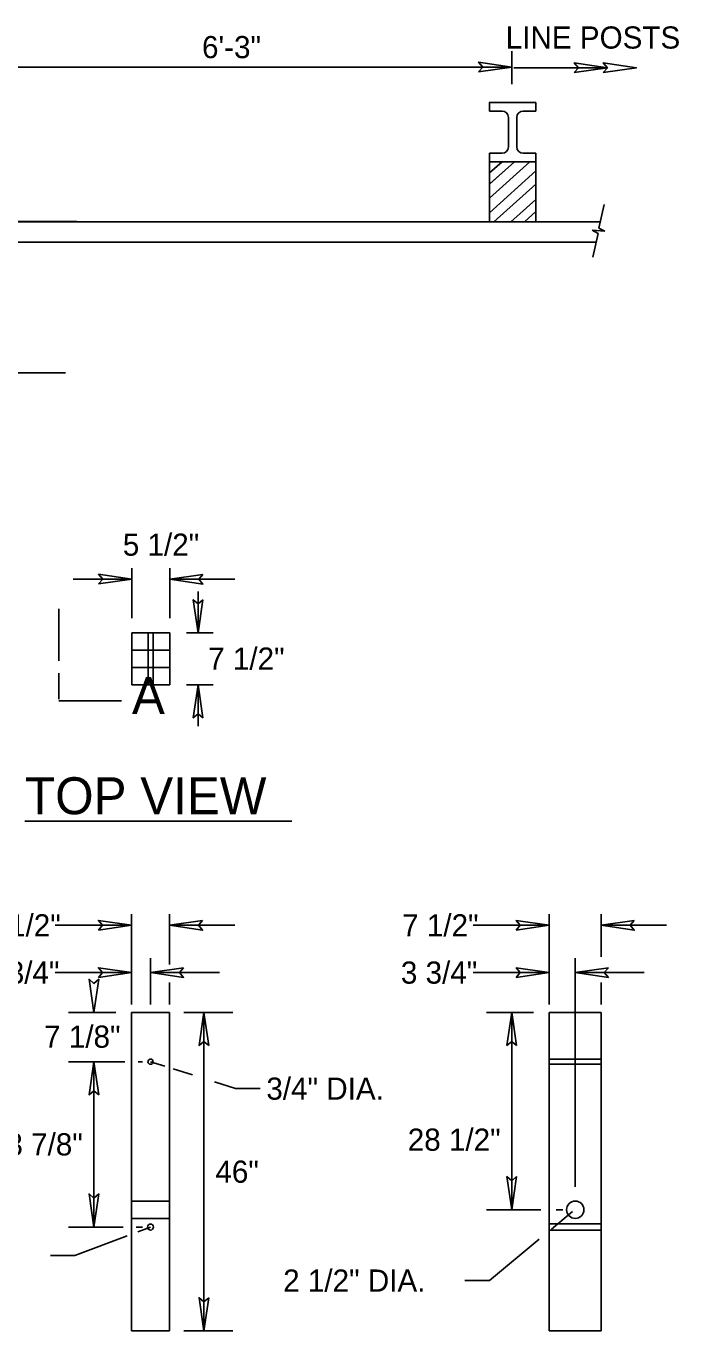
# Model space of a CAD drawing. Extents: x 12.2 to 54.5, y -7.8 to 16.1.
# Drawn here: x 15.188 to 16.956, y 9.039 to 12.571 of the extents above; entities that cross this region are included whole.
import ezdxf

# ---------------------------------------------------------------- set-up
doc = ezdxf.new("R2010")
doc.units = 0
for name, color, linetype in [('BORD-LINE', 7, 'Continuous'), ('DETAIL DIM', 7, 'Continuous'), ('DETL-DIMS', 7, 'Continuous'), ('DETL-LINE', 7, 'Continuous'), ('DETL-NOTE', 7, 'Continuous'), ('DETL-TITL', 7, 'Continuous')]:
    doc.layers.add(name, color=color, linetype=linetype)

msp = doc.modelspace()

# ---------------------------------------------------------------- linework, layer by layer
at = {"layer": 'BORD-LINE'}
for p, q in [((16.7391, 12.0246), (16.7531, 12.0888)), ((16.7435, 12.0412), (12.8535, 12.0414)), ((15.3256, 12.0419), (15.1457, 12.0419)), ((15.3257, 12.0417), (15.1457, 12.0417)), ((16.7205, 12.0189), (16.7555, 12.016)), ((16.7369, 12.0103), (16.7205, 12.0189)), ((16.7555, 12.016), (16.7391, 12.0246)), ((16.7308, 11.9868), (12.7636, 11.9868)), ((16.7229, 11.9461), (16.7369, 12.0103)), ((15.5768, 10.9288), (15.4737, 10.9288)), ((15.4737, 10.9288), (15.4737, 10.7882)), ((15.5768, 10.7882), (15.5768, 10.9288)), ((15.4737, 10.7882), (15.5768, 10.7882)), ((15.4732, 9.9011), (15.4732, 9.0386)), ((15.4732, 9.9011), (15.5763, 9.9011)), ((15.5763, 9.9011), (15.5763, 9.0386)), ((16.6047, 9.9011), (16.6047, 9.0386)), ((16.6047, 9.9011), (16.7453, 9.9011)), ((16.7453, 9.9011), (16.7453, 9.0386)), ((15.4732, 9.0386), (15.5763, 9.0386)), ((16.6047, 9.0386), (16.7453, 9.0386))]:
    msp.add_line(p, q, dxfattribs=at)
for centre, radius in [((15.5247, 9.7675), 0.00703), ((16.675, 9.3667), 0.0234), ((15.5247, 9.3198), 0.0082)]:
    msp.add_circle(centre, radius, dxfattribs=at)
for points in [[(15.5182, 10.9288), (15.5182, 10.7882)], [(15.5323, 10.7882), (15.5323, 10.9288)], [(15.5768, 10.8819), (15.4737, 10.8819)], [(15.4737, 10.8351), (15.5768, 10.8351)], [(16.7453, 9.7745), (16.6047, 9.7745)], [(16.6047, 9.7605), (16.7453, 9.7605)], [(15.5763, 9.3902), (15.4732, 9.3902)], [(15.4732, 9.3433), (15.5763, 9.3433)], [(16.7453, 9.3281), (16.6047, 9.3281)], [(16.6047, 9.3116), (16.7453, 9.3116)]]:
    msp.add_open_spline(points, degree=1, dxfattribs=at)
at = {"layer": 'DETAIL DIM'}
for p, q in [((15.4737, 10.9683), (15.4737, 11.1038)), ((15.5768, 10.9683), (15.5768, 11.1038)), ((15.3151, 11.074), (15.4737, 11.074)), ((15.7534, 11.074), (15.5768, 11.074)), ((15.6537, 10.9288), (15.6537, 11.041)), ((15.6221, 10.9288), (15.6942, 10.9288)), ((15.6221, 10.7882), (15.6942, 10.7882)), ((15.6537, 10.7882), (15.6537, 10.676)), ((15.4732, 9.9219), (15.4732, 10.1665)), ((15.5763, 10.031), (15.5763, 10.1665)), ((15.2668, 10.1367), (15.4732, 10.1367)), ((15.7529, 10.1367), (15.5763, 10.1367)), ((16.3983, 10.1367), (16.6047, 10.1367)), ((16.9219, 10.1367), (16.7453, 10.1367)), ((15.5247, 9.9219), (15.5247, 10.0482)), ((15.2668, 10.0088), (15.4732, 10.0088)), ((15.7116, 10.0088), (15.5247, 10.0088)), ((16.3983, 10.0088), (16.6047, 10.0088)), ((16.8619, 10.0088), (16.675, 10.0088)), ((15.5763, 9.9219), (15.5763, 9.9816)), ((15.3029, 9.9011), (15.4306, 9.9011)), ((15.6146, 9.9011), (15.7476, 9.9011)), ((15.6693, 9.0386), (15.6693, 9.9011)), ((16.5029, 9.3667), (16.5029, 9.9011)), ((15.3029, 9.7675), (15.4553, 9.7675)), ((15.3714, 9.7675), (15.3714, 9.3198)), ((15.4913, 9.7675), (15.5031, 9.7675)), ((15.5633, 9.7553), (15.5247, 9.7675)), ((15.6387, 9.7315), (15.5865, 9.748)), ((15.7553, 9.6946), (15.6984, 9.7126)), ((15.7553, 9.6946), (15.8218, 9.6946)), ((16.4344, 9.3667), (16.5817, 9.3667)), ((16.6229, 9.3667), (16.641, 9.3667)), ((15.3029, 9.3198), (15.4504, 9.3198)), ((15.32, 9.2431), (15.4616, 9.2962)), ((15.4855, 9.3198), (15.5031, 9.3198)), ((15.4907, 9.3071), (15.5245, 9.3198)), ((15.32, 9.2431), (15.2536, 9.2431))]:
    msp.add_line(p, q, dxfattribs=at)
at = {"layer": 'DETL-DIMS'}
for p, q in [((16.4132, 12.4738), (16.5028, 12.4606)), ((16.4132, 12.4738), (16.4243, 12.4606)), ((16.5028, 12.5036), (16.5028, 12.4143)), ((16.6724, 12.472), (16.762, 12.4588)), ((16.6724, 12.472), (16.6835, 12.4588)), ((16.7509, 12.472), (16.8405, 12.4588)), ((16.7509, 12.472), (16.762, 12.4588)), ((16.5028, 12.4606), (15.098, 12.4606)), ((16.4132, 12.4477), (16.5028, 12.4606)), ((16.4132, 12.4477), (16.4243, 12.4606)), ((16.762, 12.4588), (16.5084, 12.4588)), ((16.6724, 12.4459), (16.762, 12.4588)), ((16.6724, 12.4459), (16.6835, 12.4588)), ((16.7509, 12.4459), (16.8405, 12.4588)), ((16.7509, 12.4459), (16.762, 12.4588)), ((15.3841, 11.0872), (15.4737, 11.074)), ((15.3841, 11.0872), (15.3952, 11.074)), ((15.3841, 11.0611), (15.4737, 11.074)), ((15.3841, 11.0611), (15.3952, 11.074)), ((15.6664, 11.0869), (15.5768, 11.074)), ((15.6664, 11.0608), (15.5768, 11.074)), ((15.6664, 11.0869), (15.6553, 11.074)), ((15.6664, 11.0608), (15.6553, 11.074)), ((15.2761, 10.8528), (15.2761, 10.9935)), ((15.6405, 11.0184), (15.6537, 10.9288)), ((15.6405, 11.0184), (15.6537, 11.0073)), ((15.6666, 11.0184), (15.6537, 10.9288)), ((15.6666, 11.0184), (15.6537, 11.0073)), ((15.2767, 10.7489), (15.2767, 10.8197)), ((15.6405, 10.6986), (15.6537, 10.7882)), ((15.6666, 10.6986), (15.6537, 10.7882)), ((15.446, 10.7448), (15.2767, 10.7448)), ((15.6405, 10.6986), (15.6537, 10.7097)), ((15.6666, 10.6986), (15.6537, 10.7097)), ((15.3836, 10.1499), (15.4732, 10.1367)), ((15.3836, 10.1499), (15.3947, 10.1367)), ((15.6659, 10.1496), (15.5763, 10.1367)), ((15.6659, 10.1496), (15.6548, 10.1367)), ((16.5151, 10.1499), (16.6047, 10.1367)), ((16.5151, 10.1499), (16.5262, 10.1367)), ((16.6047, 9.9219), (16.6047, 10.1665)), ((16.7453, 10.0518), (16.7453, 10.1665)), ((16.8349, 10.1496), (16.7453, 10.1367)), ((16.8349, 10.1496), (16.8238, 10.1367)), ((15.3836, 10.1238), (15.4732, 10.1367)), ((15.3836, 10.1238), (15.3947, 10.1367)), ((15.6659, 10.1235), (15.5763, 10.1367)), ((15.6659, 10.1235), (15.6548, 10.1367)), ((16.5151, 10.1238), (16.6047, 10.1367)), ((16.5151, 10.1238), (16.5262, 10.1367)), ((16.8349, 10.1235), (16.7453, 10.1367)), ((16.8349, 10.1235), (16.8238, 10.1367)), ((16.675, 9.4286), (16.675, 10.0482)), ((15.3836, 10.022), (15.4732, 10.0088)), ((15.3836, 10.022), (15.3947, 10.0088)), ((15.3836, 9.9959), (15.4732, 10.0088)), ((15.3836, 9.9959), (15.3947, 10.0088)), ((15.6143, 10.0217), (15.5247, 10.0088)), ((15.6143, 9.9956), (15.5247, 10.0088)), ((15.6143, 10.0217), (15.6032, 10.0088)), ((15.6143, 9.9956), (15.6032, 10.0088)), ((16.5151, 10.022), (16.6047, 10.0088)), ((16.5151, 10.022), (16.5262, 10.0088)), ((16.5151, 9.9959), (16.6047, 10.0088)), ((16.5151, 9.9959), (16.5262, 10.0088)), ((16.7646, 10.0217), (16.675, 10.0088)), ((16.7646, 9.9956), (16.675, 10.0088)), ((16.7646, 10.0217), (16.7535, 10.0088)), ((16.7646, 9.9956), (16.7535, 10.0088)), ((15.3582, 9.9907), (15.3714, 9.9011)), ((15.3582, 9.9907), (15.3714, 9.9796)), ((15.3843, 9.9907), (15.3714, 9.9011)), ((15.3843, 9.9907), (15.3714, 9.9796)), ((16.7453, 9.9219), (16.7453, 9.9816)), ((15.6561, 9.8115), (15.6693, 9.9011)), ((15.6822, 9.8115), (15.6693, 9.9011)), ((16.4344, 9.9011), (16.5621, 9.9011)), ((16.4897, 9.8115), (16.5029, 9.9011)), ((16.5158, 9.8115), (16.5029, 9.9011)), ((15.6561, 9.8115), (15.6693, 9.8226)), ((15.6822, 9.8115), (15.6693, 9.8226)), ((16.4897, 9.8115), (16.5029, 9.8226)), ((16.5158, 9.8115), (16.5029, 9.8226)), ((15.3582, 9.6779), (15.3714, 9.7675)), ((15.3843, 9.6779), (15.3714, 9.7675)), ((15.3582, 9.6779), (15.3714, 9.689)), ((15.3843, 9.6779), (15.3714, 9.689)), ((16.4897, 9.4563), (16.5029, 9.3667)), ((16.4897, 9.4563), (16.5029, 9.4452)), ((16.5158, 9.4563), (16.5029, 9.3667)), ((16.5158, 9.4563), (16.5029, 9.4452)), ((15.3582, 9.4094), (15.3714, 9.3198)), ((15.3582, 9.4094), (15.3714, 9.3983)), ((15.3843, 9.4094), (15.3714, 9.3198)), ((15.3843, 9.4094), (15.3714, 9.3983)), ((16.6106, 9.3143), (16.6679, 9.3619)), ((16.4428, 9.1749), (16.5775, 9.2868)), ((16.4428, 9.1749), (16.3763, 9.1749)), ((15.6561, 9.1282), (15.6693, 9.0386)), ((15.6561, 9.1282), (15.6693, 9.1171)), ((15.6822, 9.1282), (15.6693, 9.0386)), ((15.6822, 9.1282), (15.6693, 9.1171)), ((15.6146, 9.0386), (15.7476, 9.0386))]:
    msp.add_line(p, q, dxfattribs=at)
for points in [[(16.4132, 12.4477), (16.5028, 12.4606), (16.4132, 12.4738), (16.4243, 12.4606)], [(16.6724, 12.4459), (16.762, 12.4588), (16.6724, 12.472), (16.6835, 12.4588)], [(16.7509, 12.4459), (16.8405, 12.4588), (16.7509, 12.472), (16.762, 12.4588)], [(15.3841, 11.0611), (15.4737, 11.074), (15.3841, 11.0872), (15.3952, 11.074)], [(15.6664, 11.0869), (15.5768, 11.074), (15.6664, 11.0608), (15.6553, 11.074)], [(15.6666, 11.0184), (15.6537, 10.9288), (15.6405, 11.0184), (15.6537, 11.0073)], [(15.6666, 10.6986), (15.6537, 10.7882), (15.6405, 10.6986), (15.6537, 10.7097)], [(15.3836, 10.1238), (15.4732, 10.1367), (15.3836, 10.1499), (15.3947, 10.1367)], [(15.6659, 10.1496), (15.5763, 10.1367), (15.6659, 10.1235), (15.6548, 10.1367)], [(16.5151, 10.1238), (16.6047, 10.1367), (16.5151, 10.1499), (16.5262, 10.1367)], [(16.8349, 10.1496), (16.7453, 10.1367), (16.8349, 10.1235), (16.8238, 10.1367)], [(15.3836, 9.9959), (15.4732, 10.0088), (15.3836, 10.022), (15.3947, 10.0088)], [(15.6143, 10.0217), (15.5247, 10.0088), (15.6143, 9.9956), (15.6032, 10.0088)], [(16.5151, 9.9959), (16.6047, 10.0088), (16.5151, 10.022), (16.5262, 10.0088)], [(16.7646, 10.0217), (16.675, 10.0088), (16.7646, 9.9956), (16.7535, 10.0088)], [(15.3843, 9.9907), (15.3714, 9.9011), (15.3582, 9.9907), (15.3714, 9.9796)], [(15.6822, 9.8115), (15.6693, 9.9011), (15.6561, 9.8115), (15.6693, 9.8226)], [(16.5158, 9.8115), (16.5029, 9.9011), (16.4897, 9.8115), (16.5029, 9.8226)], [(15.3843, 9.6779), (15.3714, 9.7675), (15.3582, 9.6779), (15.3714, 9.689)], [(16.5158, 9.4563), (16.5029, 9.3667), (16.4897, 9.4563), (16.5029, 9.4452)], [(15.3843, 9.4094), (15.3714, 9.3198), (15.3582, 9.4094), (15.3714, 9.3983)], [(15.6822, 9.1282), (15.6693, 9.0386), (15.6561, 9.1282), (15.6693, 9.1171)]]:
    msp.add_lwpolyline(points, close=True, dxfattribs=at)
at = {"layer": 'DETL-LINE'}
for p, q in [((16.5683, 12.3644), (16.4421, 12.3644)), ((16.4424, 12.3414), (16.4424, 12.3644)), ((16.4424, 12.3414), (16.4767, 12.3414)), ((16.5339, 12.3414), (16.5683, 12.3414)), ((16.5683, 12.3414), (16.5683, 12.3644)), ((16.4939, 12.2843), (16.4939, 12.3243)), ((16.5167, 12.2843), (16.5167, 12.3243)), ((16.4939, 12.2843), (16.4939, 12.2442)), ((16.5167, 12.2843), (16.5167, 12.2442)), ((16.4424, 12.0412), (16.4424, 12.2271)), ((16.4424, 12.2271), (16.4424, 12.2042)), ((16.4424, 12.2271), (16.4767, 12.2271)), ((16.5339, 12.2271), (16.5683, 12.2271)), ((16.5683, 12.2271), (16.5683, 12.2042)), ((16.5683, 12.2042), (16.442, 12.2042)), ((16.5683, 12.2042), (16.442, 12.2042)), ((16.4423, 12.1051), (16.5524, 12.2042)), ((16.4428, 12.1433), (16.5104, 12.2042)), ((16.4428, 12.1737), (16.4767, 12.2042)), ((16.4446, 12.145), (16.5104, 12.2042)), ((16.5683, 12.0412), (16.5683, 12.2042)), ((16.4424, 12.0662), (16.5686, 12.1798)), ((16.4549, 12.0415), (16.5685, 12.1438)), ((16.5007, 12.0412), (16.5683, 12.102)), ((16.5371, 12.0412), (16.5683, 12.0692))]:
    msp.add_line(p, q, dxfattribs=at)
for centre, start, end in [((16.4767, 12.3243), 360, 90), ((16.5339, 12.3243), 90, 180), ((16.4767, 12.2442), 270, 360), ((16.5339, 12.2442), 180, 270)]:
    msp.add_arc(centre, 0.0172, start, end, dxfattribs=at)
at = {"layer": 'DETL-TITL'}
for p, q in [((14.4202, 11.6328), (15.2947, 11.6328)), ((15.1843, 10.419), (15.9076, 10.419))]:
    msp.add_line(p, q, dxfattribs=at)

# ---------------------------------------------------------------- texts
at = {"layer": 'DETL-NOTE'}
for s, p in [('6\'-3"', (15.6642, 12.4845)), ('LINE POSTS', (16.4867, 12.5105)), ('5 1/2"', (15.4497, 11.1374)), ('7 1/2"', (15.6809, 10.8289)), ('5 1/2"', (15.0747, 10.1067)), ('7 1/2"', (16.2062, 10.1067)), ('2 3/4"', (15.0712, 9.9788)), ('3 3/4"', (16.2027, 9.9788)), ('7 1/8"', (15.2366, 9.8053)), ('3/4" DIA.', (15.8384, 9.6646)), ('23 7/8"', (15.0898, 9.5137)), ('28 1/2"', (16.2213, 9.5264)), ('46"', (15.7004, 9.4398)), ('2 1/2" DIA.', (15.884, 9.1449))]:
    msp.add_text(s, height=0.06, dxfattribs=at).set_placement(p)
at = {"layer": 'DETL-TITL'}
for s, p in [('A', (15.4744, 10.7087)), ('TOP VIEW', (15.1849, 10.4375))]:
    msp.add_text(s, height=0.1, dxfattribs=at).set_placement(p)

doc.saveas('drawing.dxf')
